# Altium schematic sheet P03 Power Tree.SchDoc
size 297 x 209 mm
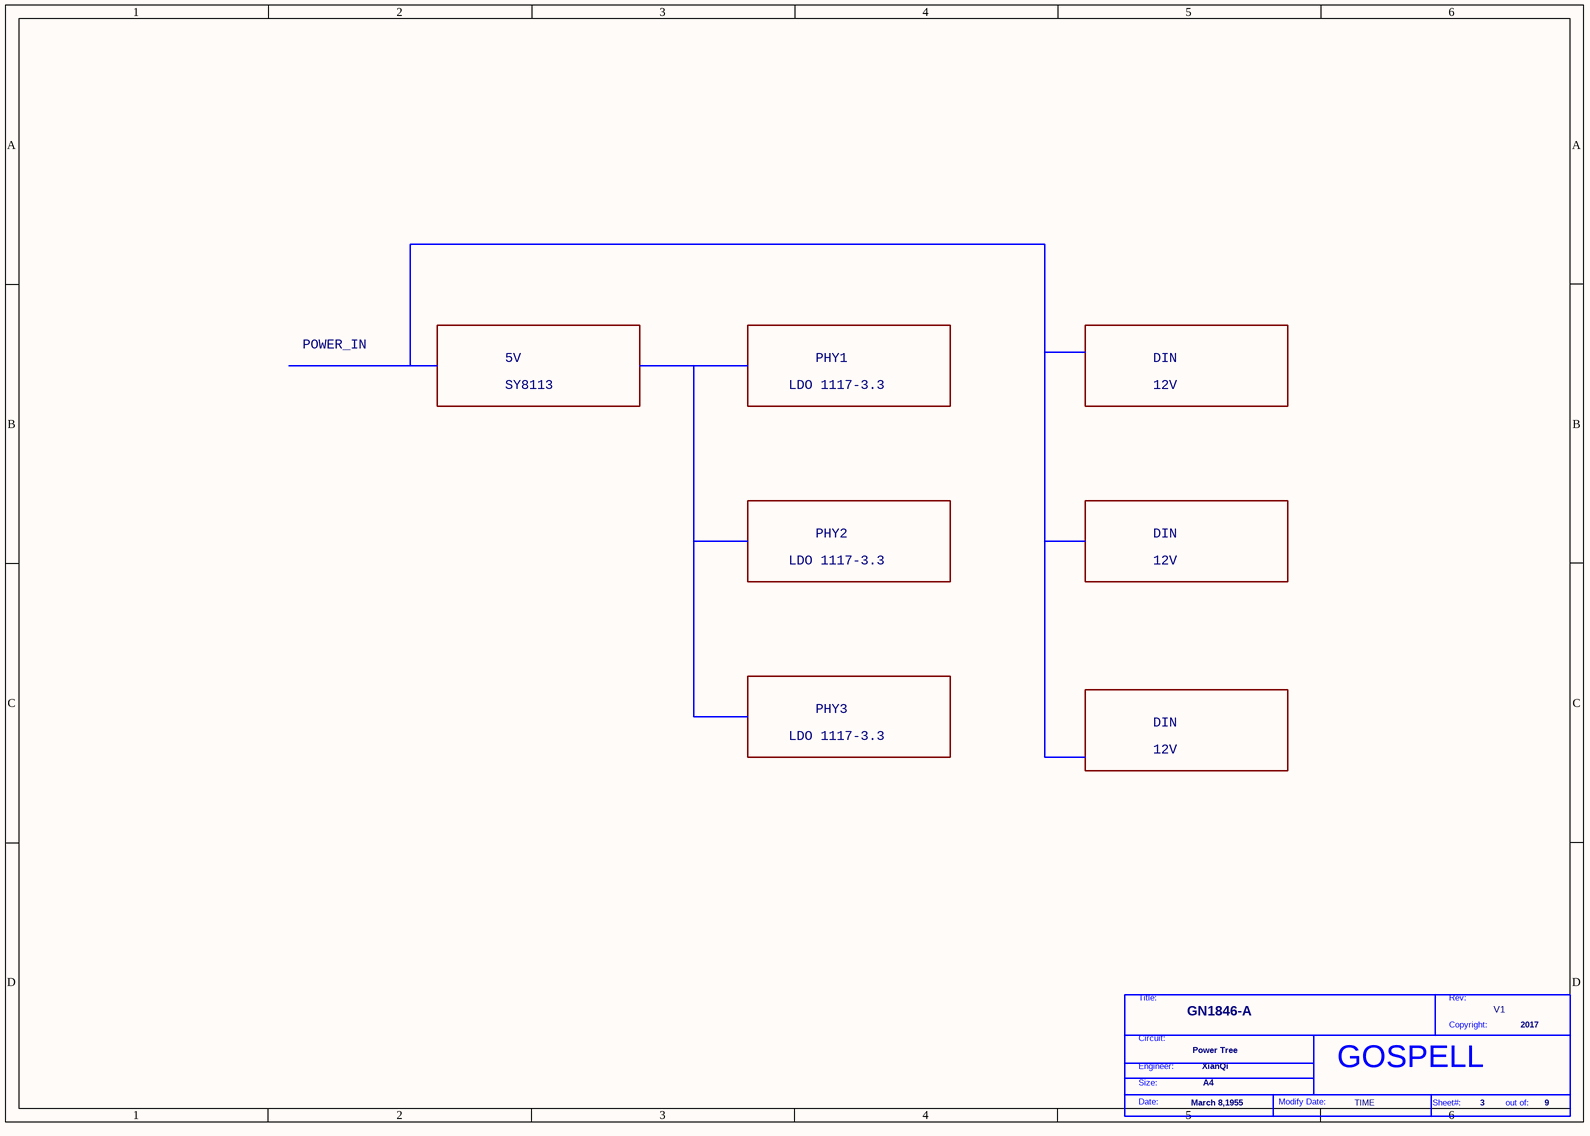
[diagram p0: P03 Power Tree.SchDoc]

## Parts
*  Doc: Power Tree  Page Count: 9  Page Number: 3  Page Create Date: March 8,1955  Page Size: A4  RevCode: V1  Title: GN1846-A  Copyright: 2017  Engineer: XianQi  Page Modify Date: TIME  (hidden comment: GOSPELL)  (graphical)

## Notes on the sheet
- POWER_IN
- 5V
- SY8113
- LDO 1117-3.3
- PHY1
- DIN
- 12V
- PHY2
- PHY3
